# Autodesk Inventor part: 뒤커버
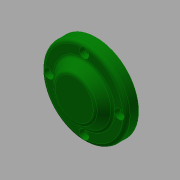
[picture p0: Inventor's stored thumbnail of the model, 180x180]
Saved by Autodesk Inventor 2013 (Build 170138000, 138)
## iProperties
Created: 2017-08
Part Number: 뒤커버
Material: 알루미늄 6061
Document SubType Name: Modeling
Designer: mduedu
Density: 1 g/cm^3
Author: mduedu
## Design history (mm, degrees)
sketch "스케치1"
  geometry: C1 r 35 at (0, 0); 1 further point
  constraints: 1 centre point, 1 coincident
  dimensions: "d0" = 70 diameter of C1
extrude "돌출1" new body sketch "스케치1" distance "d1" = 10; taper "d2" = 0 deg
sketch "스케치2"
  geometry: C1 r 24 at (0, 0); 1 further point
  constraints: 1 centre point, 1 coincident
  dimensions: "d3" = 48 diameter of C1
node "작업 평면1"
sketch "스케치3"
  geometry: C1 r 17 at (0, 0); 1 further point
  constraints: 1 centre point, 1 coincident
  dimensions: "d5" = 34 diameter of C1
feature "로프트1" sketch "스케치3" dims "d6" = 0, "d7" = 90 deg, "d8" = 0, "d9" = 90 deg
sketch "스케치4"
  geometry: C1 r 24 at (0, 0) reference; 1 further point
extrude "돌출2" join sketch "스케치4" distance "d10" = 8; taper "d11" = 0 deg
hole "구멍1" diameter "d14" = 40; stored, may be unused: countersink angle "d18" = 90 deg, drill point angle "d20" = 0 deg; dims "d12" = 10, "d13" = 10, "d15" = 6, "d16" = 4, "d17" = 2, "d19" = 12
hole "구멍2" diameter "d23" = 34; stored, may be unused: countersink angle "d27" = 90 deg, drill point angle "d29" = 0 deg; dims "d24" = 6, "d25" = 4, "d26" = 2, "d28" = 6, "d62" = 10, "d63" = 10
chamfer "모따기1" distance "d39" = 1; stored, may be unused: second distance "d40" = 2, angle "d41" = 45 deg
fillet "모깎기1" dims "d42" = 0.3
fillet "모깎기2" dims "d43" = 3
sketch "스케치5" dims "d44" = 58
  geometry: 6 further points
  constraints: 2 vertical alignment, 1 coincident, 7 other
  dimensions: "d47" = 360 deg dimension on point (0, 0) point (0, 29) (derived)
sketch "스케치6" dims "d64" = 58 (derived)
  geometry: 6 further points
  constraints: 1 coincident, 1 vertical alignment, 6 other
hole "구멍4" sketch "스케치6" at (0, 29), (-29, 0), (29, 0), (0, -29) diameter "d49" = 4.5; stored, may be unused: countersink angle "d53" = 90 deg, drill point angle "d55" = 0 deg; dims "d50" = 6, "d51" = 8, "d52" = 4.6, "d54" = 8
fillet "모깎기3" dims "d56" = 3
fillet "모깎기4" dims "d57" = 3
fillet "모깎기5" dims "d58" = 3
node "솔리드1"
other parameters: "d4" = 8
